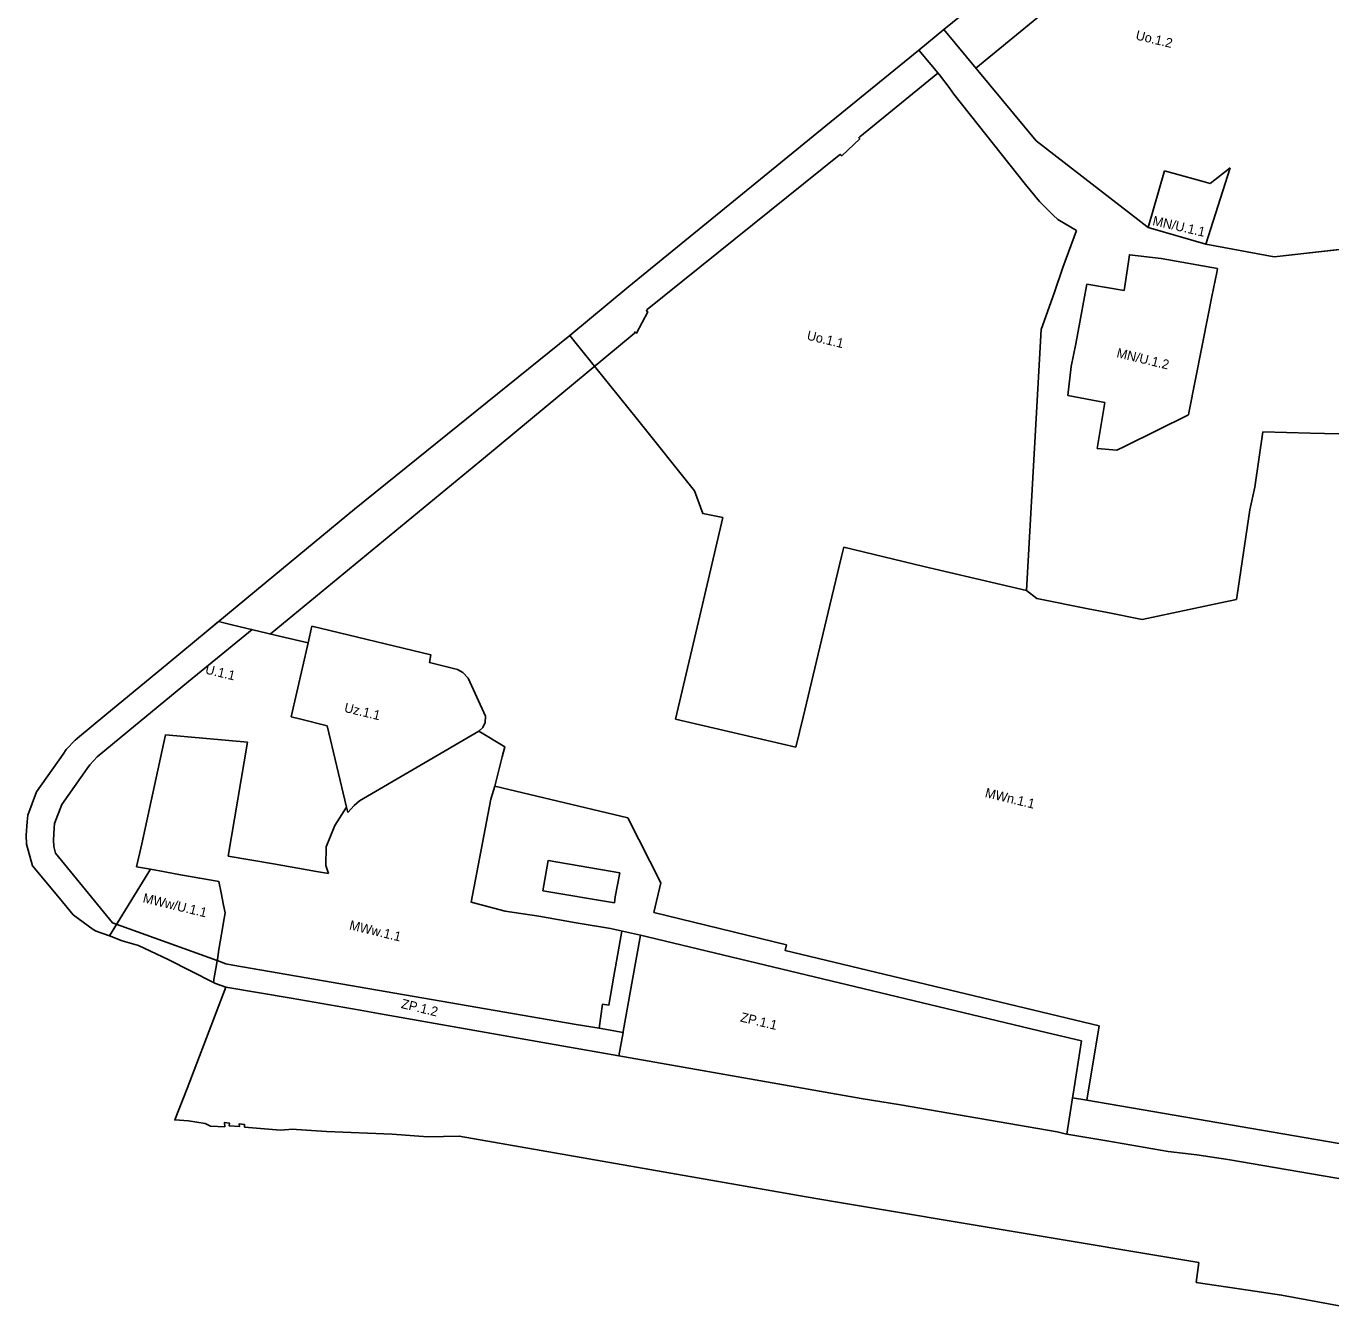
# Model space of a CAD drawing. Extents: x 7429686 to 7432896, y 5547954 to 5550600.
# Drawn here: x 7429744 to 7430296, y 5548918 to 5549462 of the extents above; entities that cross this region are included whole.
import ezdxf

# ---------------------------------------------------------------- set-up
doc = ezdxf.new("R2010")
doc.units = 0
for name, color, linetype in [('granica planu', 7, 'Continuous'), ('linie rozgraniczające', 7, 'Continuous'), ('nieprzekraczalna linia zabudowy', 7, 'Continuous'), ('obowiązująca linia zabudowy', 7, 'Continuous'), ('oznaczenia przeznaczeń', 7, 'Continuous')]:
    doc.layers.add(name, color=color, linetype=linetype)

msp = doc.modelspace()

# ---------------------------------------------------------------- linework, layer by layer
at = {"layer": 'granica planu'}
for p, q in [((7430121.7, 5549451.41), (7430132.35, 5549460.15)), ((7429999.01, 5549351.39), (7430056.21, 5549398.07)), ((7429974.03, 5549330.62), (7429999.01, 5549351.39)), ((7429765.49, 5549160.12), (7429777.91, 5549170.36)), ((7429760.77, 5549155.25), (7429764.52, 5549159.31)), ((7429764.52, 5549159.31), (7429765.49, 5549160.12)), ((7429744.41, 5549127.5), (7429748.09, 5549137.32)), ((7429746.43, 5549106.07), (7429743.96, 5549115.17)), ((7429757.87, 5549092.3), (7429746.43, 5549106.07)), ((7429763.69, 5549085.3), (7429757.87, 5549092.3)), ((7429772.14, 5549079.09), (7429763.69, 5549085.3)), ((7429784.45, 5549074.34), (7429779, 5549076.36)), ((7429811.93, 5549011.78), (7429828.35, 5549054.69)), ((7429806.7, 5548998.47), (7429811.93, 5549011.78))]:
    msp.add_line(p, q, dxfattribs=at)
for points in [[(7430132.35, 5549460.15), (7430143.42, 5549469.09), (7430236.2, 5549543.95)], [(7430056.21, 5549398.07), (7430078.56, 5549416.31), (7430121.7, 5549451.41)], [(7429848.68, 5549228.85), (7429882.8, 5549257.06), (7429974.03, 5549330.62)], [(7429777.91, 5549170.36), (7429803.51, 5549191.49), (7429820.83, 5549205.81), (7429848.68, 5549228.85)], [(7429748.09, 5549137.32), (7429759.37, 5549153.27), (7429760.77, 5549155.25)], [(7429743.96, 5549115.17), (7429743.74, 5549119.03), (7429744.17, 5549124.69), (7429744.41, 5549127.5)], [(7429779, 5549076.36), (7429773.38, 5549078.45), (7429772.14, 5549079.09)], [(7429823.05, 5549056.61), (7429803.83, 5549066.37), (7429791.39, 5549072.27), (7429784.45, 5549074.34)], [(7429828.35, 5549054.69), (7429823.91, 5549056.17), (7429823.05, 5549056.61)], [(7430311.26, 5548917.61), (7430275.35, 5548924.31), (7430261.26, 5548926.4), (7430239.24, 5548929.66), (7430240.29, 5548938.04), (7430086.5, 5548963.73), (7430074.11, 5548965.9), (7429927.19, 5548991.62), (7429913.86, 5548991.27), (7429898.7, 5548992.51), (7429870.99, 5548993.53), (7429858.19, 5548994.4), (7429856.64, 5548994.5), (7429851.45, 5548994.19), (7429836.29, 5548995.43), (7429836.24, 5548996.48), (7429834.03, 5548996.84), (7429834.07, 5548995.64), (7429829.71, 5548996.01), (7429829.81, 5548997.12), (7429827.8, 5548997.39), (7429827.87, 5548995.59), (7429821.81, 5548995.84), (7429819.61, 5548996.9), (7429812.46, 5548998.11), (7429806.7, 5548998.47)]]:
    msp.add_lwpolyline(points, dxfattribs=at)
at = {"layer": 'linie rozgraniczające'}
for p, q in [((7430132.35, 5549460.15), (7430121.7, 5549451.41)), ((7430171.48, 5549413.08), (7430132.35, 5549460.15)), ((7430130.53, 5549440.9), (7430121.7, 5549451.41)), ((7430121.7, 5549451.41), (7430130.53, 5549440.9)), ((7430134.67, 5549435.54), (7430130.53, 5549440.9)), ((7430130.53, 5549440.9), (7430134.67, 5549435.54)), ((7430218.82, 5549376.39), (7430171.48, 5549413.08)), ((7430056.21, 5549398.07), (7429999.01, 5549351.39)), ((7430172.8, 5549387.39), (7430166.96, 5549394.55)), ((7430166.96, 5549394.55), (7430172.8, 5549387.39)), ((7430178.59, 5549381.57), (7430172.8, 5549387.39)), ((7430172.8, 5549387.39), (7430178.59, 5549381.57)), ((7430180.59, 5549379.72), (7430178.59, 5549381.57)), ((7430178.59, 5549381.57), (7430180.59, 5549379.72)), ((7430188.51, 5549375), (7430180.59, 5549379.72)), ((7430180.59, 5549379.72), (7430188.51, 5549375)), ((7430182.78, 5549359.32), (7430188.51, 5549375)), ((7430188.51, 5549375), (7430182.78, 5549359.32)), ((7430243.28, 5549369.29), (7430218.82, 5549376.39)), ((7430272.16, 5549363.93), (7430243.28, 5549369.29)), ((7430337.34, 5549371.27), (7430272.16, 5549363.93)), ((7430210.57, 5549361.79), (7430208.74, 5549349.63)), ((7430208.74, 5549349.63), (7430210.57, 5549361.79)), ((7430248.3, 5549359.02), (7430224.4, 5549363.17)), ((7430224.4, 5549363.17), (7430248.3, 5549359.02)), ((7430179.02, 5549348.47), (7430182.78, 5549359.32)), ((7430182.78, 5549359.32), (7430179.02, 5549348.47)), ((7430245.9, 5549347.08), (7430248.02, 5549357.28)), ((7430248.02, 5549357.28), (7430245.9, 5549347.08)), ((7430248.02, 5549357.28), (7430248.3, 5549359.02)), ((7430248.3, 5549359.02), (7430248.02, 5549357.28)), ((7429999.01, 5549351.39), (7429974.03, 5549330.62)), ((7430192.91, 5549352.39), (7430188.25, 5549327.09)), ((7430188.25, 5549327.09), (7430192.91, 5549352.39)), ((7430208.74, 5549349.63), (7430192.91, 5549352.39)), ((7430192.91, 5549352.39), (7430208.74, 5549349.63)), ((7430173.52, 5549333.2), (7430179.02, 5549348.47)), ((7430179.02, 5549348.47), (7430173.52, 5549333.2)), ((7430244.48, 5549339.91), (7430245.9, 5549347.08)), ((7430245.9, 5549347.08), (7430244.48, 5549339.91)), ((7429974.03, 5549330.62), (7429976.7, 5549327.18)), ((7429976.7, 5549327.18), (7429974.03, 5549330.62)), ((7430167.4, 5549222.59), (7430173.52, 5549333.2)), ((7430173.52, 5549333.2), (7430167.4, 5549222.59)), ((7430188.25, 5549327.09), (7430186.33, 5549317.5)), ((7430186.33, 5549317.5), (7430188.25, 5549327.09)), ((7430186.33, 5549317.5), (7430184.79, 5549305.25)), ((7430184.79, 5549305.25), (7430186.33, 5549317.5)), ((7430184.79, 5549305.25), (7430200.5, 5549302.3)), ((7430200.5, 5549302.3), (7430184.79, 5549305.25)), ((7430200.5, 5549302.3), (7430197.33, 5549282.7)), ((7430197.33, 5549282.7), (7430200.5, 5549302.3)), ((7430002.65, 5549295.01), (7430026.84, 5549264.89)), ((7430026.84, 5549264.89), (7430002.65, 5549295.01)), ((7430209.16, 5549283.78), (7430235.99, 5549296.95)), ((7430235.99, 5549296.95), (7430209.16, 5549283.78)), ((7430263.98, 5549266.33), (7430267.43, 5549289.84)), ((7430267.43, 5549289.84), (7430263.98, 5549266.33)), ((7430197.33, 5549282.7), (7430205.6, 5549282.09)), ((7430205.6, 5549282.09), (7430197.33, 5549282.7)), ((7430205.6, 5549282.09), (7430209.16, 5549283.78)), ((7430209.16, 5549283.78), (7430205.6, 5549282.09)), ((7430261.92, 5549256.82), (7430263.98, 5549266.33)), ((7430263.98, 5549266.33), (7430261.92, 5549256.82)), ((7430038.74, 5549253.48), (7430029.55, 5549214.28)), ((7430029.55, 5549214.28), (7430038.74, 5549253.48)), ((7430089.02, 5549237.06), (7430090.02, 5549240.94)), ((7430090.02, 5549240.94), (7430089.02, 5549237.06)), ((7430090.02, 5549240.94), (7430123.88, 5549232.75)), ((7430123.88, 5549232.75), (7430090.02, 5549240.94)), ((7430084.11, 5549216.49), (7430089.02, 5549237.06)), ((7430089.02, 5549237.06), (7430084.11, 5549216.49)), ((7429848.68, 5549228.85), (7429820.83, 5549205.81)), ((7430123.88, 5549232.75), (7430167.4, 5549222.59)), ((7430167.4, 5549222.59), (7430123.88, 5549232.75)), ((7430249.45, 5549217.35), (7430256.24, 5549218.78)), ((7430256.24, 5549218.78), (7430249.45, 5549217.35)), ((7430029.55, 5549214.28), (7430018.72, 5549168.1)), ((7430018.72, 5549168.1), (7430029.55, 5549214.28)), ((7430072.77, 5549169.01), (7430084.11, 5549216.49)), ((7430084.11, 5549216.49), (7430072.77, 5549169.01)), ((7430216.33, 5549210.38), (7430249.45, 5549217.35)), ((7430249.45, 5549217.35), (7430216.33, 5549210.38)), ((7429820.83, 5549205.81), (7429825.26, 5549209.47)), ((7429825.26, 5549209.47), (7429830.92, 5549208.15)), ((7429830.92, 5549208.15), (7429851.62, 5549203.1)), ((7429863.18, 5549200.54), (7429864.79, 5549207.5)), ((7429864.79, 5549207.5), (7429915.14, 5549195.33)), ((7429851.62, 5549203.1), (7429863.18, 5549200.54)), ((7429915.14, 5549195.33), (7429914.5, 5549192.21)), ((7429914.5, 5549192.21), (7429926.47, 5549189.22)), ((7429926.47, 5549189.22), (7429928.68, 5549187.95)), ((7429928.68, 5549187.95), (7429930.89, 5549185.5)), ((7429930.89, 5549185.5), (7429938.23, 5549169.36)), ((7429938.23, 5549169.36), (7429938.11, 5549166.72)), ((7430018.72, 5549168.1), (7430069.73, 5549156.29)), ((7430069.73, 5549156.29), (7430018.72, 5549168.1)), ((7430069.73, 5549156.29), (7430072.77, 5549169.01)), ((7430072.77, 5549169.01), (7430069.73, 5549156.29)), ((7429937.15, 5549164.68), (7429935.46, 5549163.1)), ((7429935.46, 5549163.1), (7429946.46, 5549156.4)), ((7429938.11, 5549166.72), (7429937.15, 5549164.68)), ((7429945.38, 5549152.22), (7429942.16, 5549139.79)), ((7429946.46, 5549156.4), (7429945.38, 5549152.22)), ((7429942.16, 5549139.79), (7429940.52, 5549134.32)), ((7429940.52, 5549134.32), (7429932.17, 5549090.7)), ((7429976.71, 5549081.93), (7429991.19, 5549079.47)), ((7429991.19, 5549079.47), (7430003.86, 5549076.74)), ((7429779, 5549076.36), (7429784.45, 5549074.34)), ((7429784.45, 5549074.34), (7429791.39, 5549072.27)), ((7429791.39, 5549072.27), (7429803.83, 5549066.37)), ((7429803.83, 5549066.37), (7429823.05, 5549056.61)), ((7430186.82, 5549007.78), (7430192.86, 5549006.79))]:
    msp.add_line(p, q, dxfattribs=at)
for points in [[(7430254.55, 5549558.75), (7430236.2, 5549543.95), (7430143.42, 5549469.09), (7430132.35, 5549460.15), (7430171.48, 5549413.08), (7430218.82, 5549376.39)], [(7430121.7, 5549451.41), (7430078.56, 5549416.31), (7430056.21, 5549398.07)], [(7430166.96, 5549394.55), (7430136.56, 5549432.71), (7430134.67, 5549435.54)], [(7430134.67, 5549435.54), (7430136.56, 5549432.71), (7430166.96, 5549394.55)], [(7430218.82, 5549376.39), (7430225.81, 5549400.38)], [(7430225.81, 5549400.38), (7430242.21, 5549395.81)], [(7430253.58, 5549401.55), (7430243.28, 5549369.29)], [(7430245.19, 5549394.98), (7430253.58, 5549401.55)], [(7430242.21, 5549395.81), (7430245.19, 5549394.98)], [(7430218.82, 5549376.39), (7430243.28, 5549369.29)], [(7430243.28, 5549369.29), (7430272.16, 5549363.93), (7430337.34, 5549371.27)], [(7430224.4, 5549363.17), (7430210.97, 5549364.8), (7430210.57, 5549361.79)], [(7430210.57, 5549361.79), (7430210.97, 5549364.8), (7430224.4, 5549363.17)], [(7430235.99, 5549296.95), (7430236.16, 5549297.92), (7430244.48, 5549339.91)], [(7430244.48, 5549339.91), (7430236.16, 5549297.92), (7430235.99, 5549296.95)], [(7429974.03, 5549330.62), (7429882.8, 5549257.06), (7429848.68, 5549228.85)], [(7429976.7, 5549327.18), (7429994.4, 5549305.23), (7430002.65, 5549295.01)], [(7430002.65, 5549295.01), (7429994.4, 5549305.23), (7429976.7, 5549327.18)], [(7430267.43, 5549289.84), (7430287.43, 5549289.21), (7430299.57, 5549289)], [(7430299.57, 5549289), (7430287.43, 5549289.21), (7430267.43, 5549289.84)], [(7430026.84, 5549264.89), (7430030.36, 5549255.23), (7430038.74, 5549253.48)], [(7430038.74, 5549253.48), (7430030.36, 5549255.23), (7430026.84, 5549264.89)], [(7430256.24, 5549218.78), (7430256.95, 5549223.51), (7430261.92, 5549256.82)], [(7430261.92, 5549256.82), (7430256.95, 5549223.51), (7430256.24, 5549218.78)], [(7430167.4, 5549222.59), (7430171.8, 5549219.23), (7430193.53, 5549214.91)], [(7430193.53, 5549214.91), (7430171.8, 5549219.23), (7430167.4, 5549222.59)], [(7430193.53, 5549214.91), (7430201.62, 5549213.3), (7430216.33, 5549210.38)], [(7430216.33, 5549210.38), (7430201.62, 5549213.3), (7430193.53, 5549214.91)], [(7429863.18, 5549200.54), (7429851.62, 5549203.1), (7429830.92, 5549208.15), (7429825.26, 5549209.47), (7429820.83, 5549205.81), (7429803.51, 5549191.49), (7429777.91, 5549170.36), (7429765.49, 5549160.12), (7429764.52, 5549159.31), (7429760.77, 5549155.25), (7429759.37, 5549153.27), (7429748.09, 5549137.32), (7429744.41, 5549127.5), (7429744.17, 5549124.69), (7429743.74, 5549119.03), (7429743.96, 5549115.17), (7429746.43, 5549106.07), (7429757.87, 5549092.3), (7429763.69, 5549085.3), (7429772.14, 5549079.09), (7429773.38, 5549078.45), (7429779, 5549076.36)], [(7429935.46, 5549163.1), (7429937.15, 5549164.68), (7429938.11, 5549166.72), (7429938.23, 5549169.36), (7429930.89, 5549185.5), (7429928.68, 5549187.95), (7429926.47, 5549189.22), (7429914.5, 5549192.21), (7429915.14, 5549195.33), (7429864.79, 5549207.5), (7429863.18, 5549200.54)], [(7429855.95, 5549169.12), (7429863.18, 5549200.54)], [(7429860.13, 5549168.1), (7429855.95, 5549169.12)], [(7429871.19, 5549165.39), (7429860.13, 5549168.1)], [(7429875.32, 5549148.14), (7429871.19, 5549165.39)], [(7429935.46, 5549163.1), (7429884.93, 5549133.54)], [(7430003.86, 5549076.74), (7429991.19, 5549079.47), (7429976.71, 5549081.93), (7429960.8, 5549084.73), (7429946.62, 5549086.88), (7429932.17, 5549090.7), (7429940.52, 5549134.32), (7429942.16, 5549139.79), (7429945.38, 5549152.22), (7429946.46, 5549156.4), (7429935.46, 5549163.1)], [(7429792.68, 5549115.4), (7429802.73, 5549161.53)], [(7429802.73, 5549161.53), (7429837.45, 5549158.38)], [(7429837.45, 5549158.38), (7429829.36, 5549110.11)], [(7429879.38, 5549130.9), (7429875.32, 5549148.14)], [(7429874.48, 5549123.13), (7429879.38, 5549130.9)], [(7429879.92, 5549128.66), (7429879.38, 5549130.9)], [(7429882.59, 5549131.66), (7429879.92, 5549128.66)], [(7429884.93, 5549133.54), (7429882.59, 5549131.66)], [(7429870.84, 5549114.1), (7429874.48, 5549123.13)], [(7429790.56, 5549105.68), (7429792.68, 5549115.4)], [(7429870.72, 5549106.21), (7429870.84, 5549114.1)], [(7429829.36, 5549110.11), (7429848.47, 5549106.97)], [(7429779, 5549076.36), (7429796.38, 5549104.62)], [(7429796.38, 5549104.62), (7429790.56, 5549105.68)], [(7429796.38, 5549104.62), (7429802.52, 5549103.51), (7429809.15, 5549102.31), (7429809.9, 5549102.17)], [(7429809.9, 5549102.17), (7429817.28, 5549100.83), (7429824.66, 5549099.5), (7429825.41, 5549099.36), (7429826.34, 5549094.65), (7429827.37, 5549089.42), (7429828.02, 5549086.15), (7429827.61, 5549083.7), (7429826.51, 5549077.16), (7429825.41, 5549070.62), (7429824.73, 5549066.44), (7429824.64, 5549065.94)], [(7429848.47, 5549106.97), (7429866.78, 5549103.65)], [(7429866.78, 5549103.65), (7429871.75, 5549102.74)], [(7429871.75, 5549102.74), (7429870.72, 5549106.21)], [(7429932.17, 5549090.7), (7429946.62, 5549086.88), (7429960.8, 5549084.73), (7429976.71, 5549081.93)], [(7430000.53, 5549057.95), (7430003.86, 5549076.74)], [(7430003.86, 5549076.74), (7430175.69, 5549035.49), (7430190.62, 5549031.91)], [(7430186.82, 5549007.78), (7430187.08, 5549009.41), (7430190.62, 5549031.91), (7430175.69, 5549035.49), (7430003.86, 5549076.74)], [(7429824.33, 5549064.08), (7429823.28, 5549057.93), (7429823.21, 5549057.54), (7429823.05, 5549056.61)], [(7429824.64, 5549065.94), (7429824.33, 5549064.08)], [(7429824.64, 5549065.94), (7429828.32, 5549064.55)], [(7429828.32, 5549064.55), (7429831.27, 5549064.05)], [(7429831.27, 5549064.05), (7429976.66, 5549038.86)], [(7429996.62, 5549035.93), (7430000.53, 5549057.95)], [(7429828.35, 5549054.69), (7429811.93, 5549011.78), (7429806.7, 5548998.47), (7429812.46, 5548998.11), (7429819.61, 5548996.9), (7429821.81, 5548995.84), (7429827.87, 5548995.59), (7429827.8, 5548997.39), (7429829.81, 5548997.12), (7429829.71, 5548996.01), (7429834.07, 5548995.64), (7429834.03, 5548996.84), (7429836.24, 5548996.48), (7429836.29, 5548995.43), (7429851.45, 5548994.19), (7429856.64, 5548994.5), (7429858.19, 5548994.4), (7429870.99, 5548993.53), (7429898.7, 5548992.51), (7429913.86, 5548991.27), (7429927.19, 5548991.62), (7430074.11, 5548965.9), (7430086.5, 5548963.73), (7430240.29, 5548938.04), (7430239.24, 5548929.66), (7430261.26, 5548926.4), (7430275.35, 5548924.31), (7430311.26, 5548917.61)], [(7429823.05, 5549056.61), (7429823.91, 5549056.17), (7429828.35, 5549054.69)], [(7429855.94, 5549049.96), (7429828.35, 5549054.69)], [(7429885.21, 5549044.94), (7429855.94, 5549049.96)], [(7429892.95, 5549043.57), (7429885.21, 5549044.94)], [(7429962.5, 5549031.27), (7429892.95, 5549043.57)], [(7429976.66, 5549038.86), (7429986.36, 5549037.32)], [(7429986.36, 5549037.32), (7429996.53, 5549035.44)], [(7429994.78, 5549025.59), (7429996.53, 5549035.44)], [(7429996.53, 5549035.44), (7429996.62, 5549035.93)], [(7429994.78, 5549025.59), (7429962.5, 5549031.27)], [(7430190.62, 5549031.91), (7430187.08, 5549009.41), (7430186.82, 5549007.78)], [(7430097.33, 5549007.53), (7429994.78, 5549025.59)], [(7430184.42, 5548992.47), (7430186.82, 5549007.78)], [(7430429.05, 5548966.61), (7430404.02, 5548971.58), (7430392.13, 5548972.65), (7430350.14, 5548979.92), (7430308.84, 5548986.87), (7430192.86, 5549006.79), (7430186.82, 5549007.78)], [(7430113.95, 5549004.87), (7430097.33, 5549007.53)], [(7430180.29, 5548993.36), (7430113.95, 5549004.87)], [(7430192.86, 5549006.79), (7430308.84, 5548986.87), (7430350.14, 5548979.92)], [(7430183.79, 5548992.58), (7430180.29, 5548993.36)], [(7430184.42, 5548992.47), (7430183.79, 5548992.58)], [(7430201.39, 5548989.55), (7430184.42, 5548992.47)], [(7430227.29, 5548985.16), (7430201.39, 5548989.55)], [(7430239.5, 5548983.74), (7430227.29, 5548985.16)], [(7430252.65, 5548981.65), (7430239.5, 5548983.74)], [(7430292.94, 5548974.78), (7430252.65, 5548981.65)], [(7430344.12, 5548966.05), (7430292.94, 5548974.78)]]:
    msp.add_lwpolyline(points, dxfattribs=at)
at = {"layer": 'nieprzekraczalna linia zabudowy'}
for points in [[(7430129.87, 5549441.68), (7430096.74, 5549414.74), (7430096.34, 5549414.35), (7430096.75, 5549413.91), (7430089.12, 5549406.67), (7430088.5, 5549407.3), (7430088.1, 5549406.92), (7430006.77, 5549341.57), (7430006.45, 5549340.95), (7430006.96, 5549340.68), (7430002.28, 5549331.65), (7430001.49, 5549332.06), (7430001.18, 5549331.46), (7429938.33, 5549279.17), (7429847.12, 5549204.2)], [(7429839.44, 5549206.07), (7429817.94, 5549188.53), (7429812.48, 5549184.07), (7429786.89, 5549162.96), (7429773.88, 5549152.22), (7429770.74, 5549148.83), (7429769.61, 5549147.22), (7429758.86, 5549132.01), (7429755.83, 5549123.94), (7429755.68, 5549122.12), (7429755.28, 5549116.95), (7429755.43, 5549114.29), (7429756.23, 5549111.37), (7429771.42, 5549092.81)], [(7429992.84, 5549090.32), (7429993.23, 5549092.91), (7429995.14, 5549103.07), (7429964.77, 5549108.28), (7429962.61, 5549095.5)], [(7429771.42, 5549092.81), (7429780.32, 5549081.94), (7429824.64, 5549065.94)]]:
    msp.add_lwpolyline(points, dxfattribs=at)
at = {"layer": 'obowiązująca linia zabudowy'}
msp.add_line((7430198.1, 5549038.34), (7430192.86, 5549006.79), dxfattribs=at)
for points in [[(7430268.83, 5549544.74), (7430145.91, 5549443.84)], [(7429942.16, 5549139.79), (7429998.54, 5549126.37), (7430012.54, 5549098.89), (7430009.52, 5549086.26)], [(7429962.61, 5549095.5), (7429992.84, 5549090.32)], [(7430009.52, 5549086.26), (7430065.72, 5549072.6), (7430065.11, 5549070.26), (7430198.1, 5549038.34)], [(7429986.37, 5549037.31), (7429987.79, 5549047.47), (7429990.47, 5549047.05), (7429992.65, 5549059.35), (7429996.04, 5549078.43)], [(7429986.37, 5549037.31), (7429987.79, 5549047.47), (7429990.47, 5549047.05), (7429992.65, 5549059.35), (7429996.04, 5549078.43)]]:
    msp.add_lwpolyline(points, dxfattribs=at)

# ---------------------------------------------------------------- texts
at = {"layer": 'oznaczenia przeznaczeń'}
for s, rotation, p in [('Uo.1.2', 346.4891, (7430213.33, 5549455.98)), ('MN/U.1.1', 347.0609, (7430220.48, 5549377.43)), ('Uo.1.1', 346.4891, (7430074.09, 5549328.89)), ('MN/U.1.2', 346.4891, (7430205.24, 5549321.46)), ('U.1.1', 346.4891, (7429819.33, 5549187.51)), ('Uz.1.1', 346.5122, (7429878.18, 5549171.28)), ('MWn.1.1', 346.4891, (7430149.53, 5549135.22)), ('MWw/U.1.1', 346.4891, (7429792.91, 5549090.66)), ('MWw.1.1', 346.4891, (7429880.34, 5549079.2)), ('ZP.1.2', 346.4891, (7429902.26, 5549045.9)), ('ZP.1.1', 346.4891, (7430045.93, 5549040.2))]:
    msp.add_text(s, height=4, rotation=rotation, dxfattribs=at).set_placement(p)

doc.saveas('drawing.dxf')
